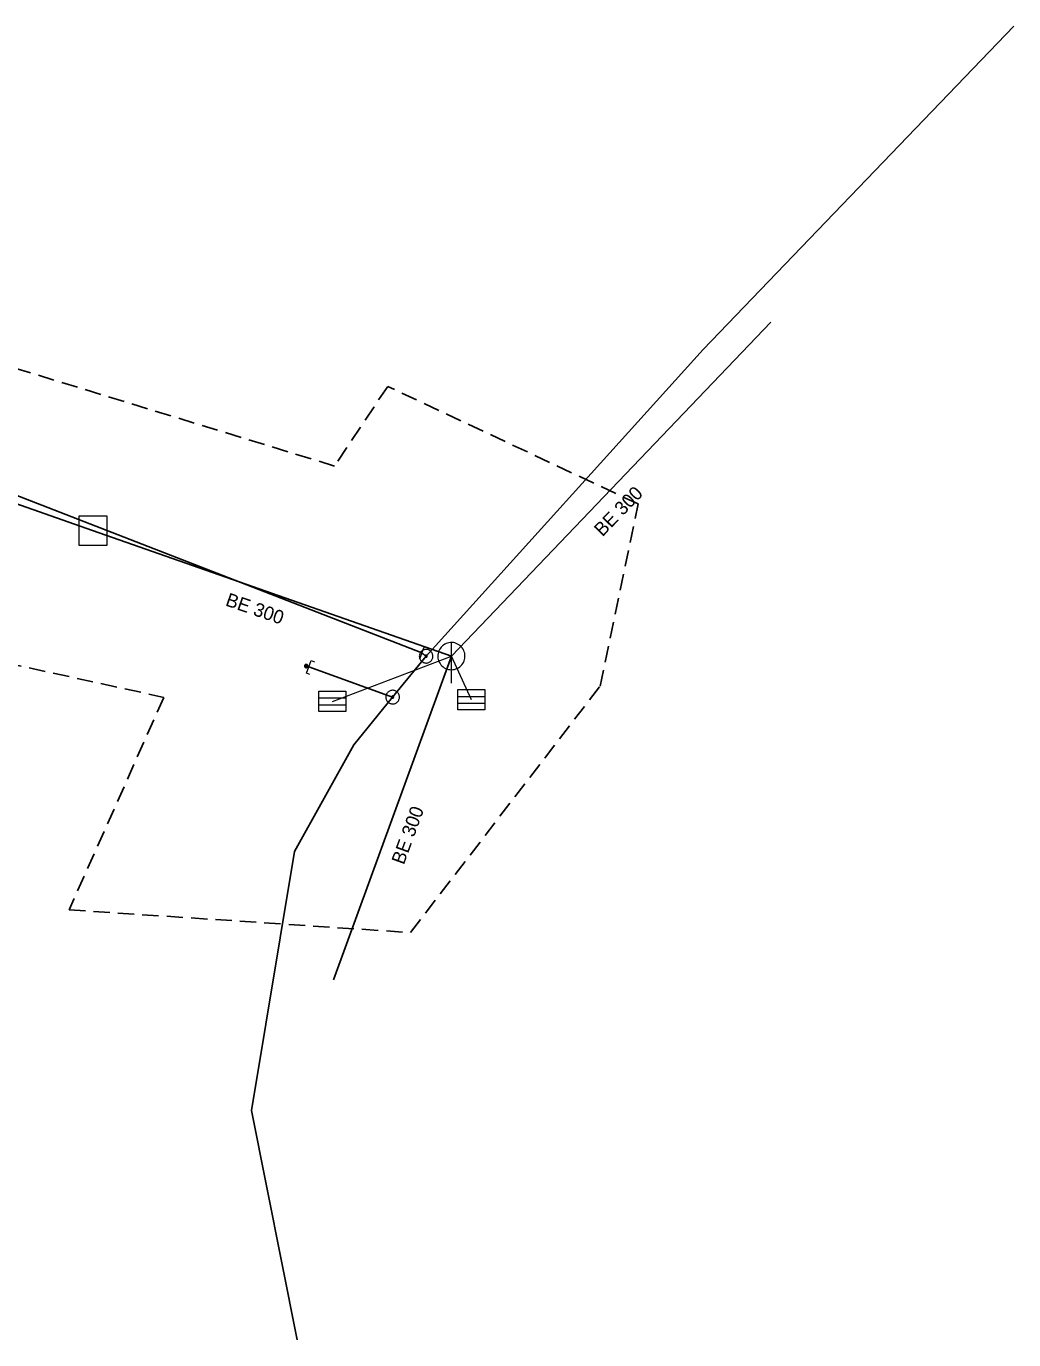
# Model space of a CAD drawing. Extents: x -687387 to -687009, y -972789 to -972578.
# Drawn here: x -687081.2 to -687008.6, y -972748.8 to -972652.2 of the extents above; entities that cross this region are included whole.
import ezdxf

# ---------------------------------------------------------------- set-up
doc = ezdxf.new("R2010")
doc.units = 0
doc.header["$LTSCALE"] = 0.4
doc.linetypes.add('MEDIUM_DASHED', pattern=[4.5, 3, -1.5])
doc.layers.add('1', color=7, linetype='Continuous')
for name, color, linetype, lineweight in [('11', 7, 'Continuous', 13), ('14', 7, 'Continuous', 25), ('17', 7, 'Continuous', 25), ('22', 7, 'Continuous', 13), ('34', 7, 'Continuous', 13), ('47', 7, 'Continuous', 13), ('63', 7, 'MEDIUM_DASHED', 25), ('9', 7, 'Continuous', 13)]:
    doc.layers.add(name, color=color, linetype=linetype, lineweight=lineweight)

msp = doc.modelspace()

# ---------------------------------------------------------------- linework, layer by layer
at = {"layer": '11'}
for p in [(-687058.699, -972701.867), (-687048.473, -972701.748)]:
    msp.add_line(p, (-687049.947, -972698.528), dxfattribs=at)
at = {"layer": '14'}
for p, q in [((-687026.435, -972673.962), (-687049.947, -972698.529)), ((-687076.354, -972689.285), (-687084.556, -972686.414)), ((-687049.947, -972698.528), (-687076.354, -972689.285)), ((-687058.628, -972722.345), (-687049.947, -972698.529))]:
    msp.add_line(p, q, dxfattribs=at)
at = {"layer": '14', "lineweight": 13}
for p, q in [((-687052.118, -972698.285), (-687051.808, -972698.538)), ((-687060.435, -972699.324), (-687060.629, -972699.259))]:
    msp.add_line(p, q, dxfattribs=at)
at = {"layer": '17'}
msp.add_line((-687054.27, -972701.546), (-687051.808, -972698.538), dxfattribs=at)
for points in [[(-687051.808, -972698.538), (-687031.429, -972675.969), (-687008.568, -972652.178)], [(-687137.189, -972675.528), (-687101.625, -972681.079), (-687082.6, -972686.438), (-687052.118, -972698.285)], [(-687061.305, -972748.839), (-687064.669, -972731.96), (-687061.487, -972712.912), (-687057.138, -972705.05), (-687054.27, -972701.546), (-687060.435, -972699.324)]]:
    msp.add_lwpolyline(points, dxfattribs=at)
at = {"layer": '22'}
for p, q in [((-687049.947, -972700.529), (-687049.946, -972697.529)), ((-687049.484, -972701.491), (-687047.484, -972701.491)), ((-687059.71, -972701.61), (-687057.71, -972701.61)), ((-687059.71, -972702.11), (-687057.71, -972702.11)), ((-687049.484, -972701.991), (-687047.484, -972701.991))]:
    msp.add_line(p, q, dxfattribs=at)
for points in [[(-687077.334, -972688.195), (-687075.301, -972688.195), (-687075.301, -972690.388), (-687077.334, -972690.388)], [(-687048.947, -972698.529), (-687048.952, -972698.42), (-687048.97, -972698.312), (-687049, -972698.206), (-687049.04, -972698.105), (-687049.092, -972698.008), (-687049.154, -972697.918), (-687049.226, -972697.835), (-687049.306, -972697.761), (-687049.394, -972697.695), (-687049.488, -972697.64), (-687049.588, -972697.595), (-687049.693, -972697.562), (-687049.8, -972697.54), (-687049.909, -972697.53), (-687050.019, -972697.532), (-687050.127, -972697.546), (-687050.234, -972697.571), (-687050.337, -972697.608), (-687050.435, -972697.657), (-687050.527, -972697.715), (-687050.613, -972697.784), (-687050.69, -972697.861), (-687050.759, -972697.947), (-687050.818, -972698.039), (-687050.866, -972698.137), (-687050.903, -972698.24), (-687050.929, -972698.347), (-687050.943, -972698.455), (-687050.946, -972698.565), (-687050.936, -972698.674), (-687050.915, -972698.781), (-687050.881, -972698.885), (-687050.837, -972698.985), (-687050.782, -972699.08), (-687050.716, -972699.168), (-687050.642, -972699.248), (-687050.559, -972699.32), (-687050.469, -972699.382), (-687050.373, -972699.434), (-687050.271, -972699.475), (-687050.166, -972699.505), (-687050.058, -972699.523), (-687049.948, -972699.529), (-687049.839, -972699.523), (-687049.731, -972699.505), (-687049.626, -972699.476), (-687049.524, -972699.435), (-687049.427, -972699.383), (-687049.337, -972699.321), (-687049.254, -972699.25), (-687049.179, -972699.17), (-687049.114, -972699.082), (-687049.058, -972698.988), (-687049.014, -972698.888), (-687048.98, -972698.784), (-687048.958, -972698.676), (-687048.948, -972698.567)], [(-687059.71, -972701.11), (-687057.71, -972701.11), (-687057.71, -972702.61), (-687059.71, -972702.61)], [(-687049.484, -972700.991), (-687047.484, -972700.991), (-687047.484, -972702.491), (-687049.484, -972702.491)]]:
    msp.add_lwpolyline(points, close=True, dxfattribs=at)
at = {"layer": '34'}
msp.add_line((-687051.951, -972697.813), (-687052.285, -972698.755), dxfattribs=at)
at = {"layer": '47'}
for points in [[(-687051.46, -972698.178), (-687051.5, -972698.144), (-687051.543, -972698.114), (-687051.588, -972698.089), (-687051.636, -972698.068), (-687051.686, -972698.052), (-687051.738, -972698.043), (-687051.79, -972698.039), (-687051.842, -972698.04), (-687051.894, -972698.045), (-687051.945, -972698.057), (-687051.995, -972698.074), (-687052.042, -972698.097), (-687052.087, -972698.123), (-687052.129, -972698.155), (-687052.167, -972698.19), (-687052.201, -972698.23), (-687052.231, -972698.273), (-687052.257, -972698.319), (-687052.277, -972698.366), (-687052.293, -972698.416), (-687052.302, -972698.468), (-687052.307, -972698.521), (-687052.306, -972698.573), (-687052.3, -972698.624), (-687052.288, -972698.675), (-687052.271, -972698.725), (-687052.249, -972698.773), (-687052.222, -972698.817), (-687052.19, -972698.859), (-687052.155, -972698.897), (-687052.115, -972698.931), (-687052.072, -972698.961), (-687052.027, -972698.988), (-687051.979, -972699.007), (-687051.929, -972699.023), (-687051.877, -972699.033), (-687051.825, -972699.038), (-687051.773, -972699.037), (-687051.721, -972699.03), (-687051.67, -972699.018), (-687051.62, -972699.001), (-687051.573, -972698.98), (-687051.528, -972698.952), (-687051.486, -972698.92), (-687051.448, -972698.885), (-687051.414, -972698.845), (-687051.384, -972698.802), (-687051.358, -972698.758), (-687051.338, -972698.709), (-687051.322, -972698.659), (-687051.312, -972698.607), (-687051.308, -972698.556), (-687051.309, -972698.503), (-687051.315, -972698.451), (-687051.327, -972698.4), (-687051.344, -972698.35), (-687051.366, -972698.304), (-687051.393, -972698.258), (-687051.425, -972698.216)], [(-687051.751, -972698.479), (-687051.757, -972698.472), (-687051.764, -972698.468), (-687051.771, -972698.464), (-687051.779, -972698.461), (-687051.788, -972698.458), (-687051.796, -972698.457), (-687051.805, -972698.455), (-687051.813, -972698.456), (-687051.822, -972698.457), (-687051.83, -972698.459), (-687051.839, -972698.462), (-687051.846, -972698.465), (-687051.853, -972698.47), (-687051.86, -972698.474), (-687051.866, -972698.481), (-687051.873, -972698.487), (-687051.877, -972698.494), (-687051.881, -972698.501), (-687051.884, -972698.509), (-687051.887, -972698.518), (-687051.888, -972698.526), (-687051.89, -972698.535), (-687051.889, -972698.543), (-687051.889, -972698.552), (-687051.886, -972698.56), (-687051.883, -972698.569), (-687051.88, -972698.576), (-687051.875, -972698.583), (-687051.871, -972698.59), (-687051.864, -972698.596), (-687051.858, -972698.603), (-687051.851, -972698.607), (-687051.844, -972698.611), (-687051.836, -972698.614), (-687051.827, -972698.617), (-687051.82, -972698.619), (-687051.81, -972698.62), (-687051.802, -972698.619), (-687051.793, -972698.619), (-687051.785, -972698.616), (-687051.776, -972698.613), (-687051.769, -972698.61), (-687051.762, -972698.605), (-687051.755, -972698.601), (-687051.749, -972698.594), (-687051.742, -972698.588), (-687051.738, -972698.581), (-687051.734, -972698.574), (-687051.731, -972698.566), (-687051.728, -972698.557), (-687051.726, -972698.55), (-687051.725, -972698.54), (-687051.726, -972698.532), (-687051.727, -972698.523), (-687051.729, -972698.515), (-687051.732, -972698.506), (-687051.735, -972698.499), (-687051.74, -972698.492), (-687051.744, -972698.485)], [(-687053.953, -972701.159), (-687053.995, -972701.128), (-687054.04, -972701.101), (-687054.088, -972701.08), (-687054.137, -972701.063), (-687054.189, -972701.052), (-687054.241, -972701.047), (-687054.293, -972701.047), (-687054.345, -972701.052), (-687054.396, -972701.062), (-687054.446, -972701.078), (-687054.495, -972701.099), (-687054.54, -972701.125), (-687054.582, -972701.155), (-687054.621, -972701.19), (-687054.656, -972701.229), (-687054.687, -972701.271), (-687054.714, -972701.316), (-687054.735, -972701.365), (-687054.752, -972701.413), (-687054.763, -972701.465), (-687054.768, -972701.517), (-687054.769, -972701.57), (-687054.764, -972701.622), (-687054.754, -972701.673), (-687054.737, -972701.722), (-687054.716, -972701.771), (-687054.69, -972701.816), (-687054.66, -972701.858), (-687054.625, -972701.897), (-687054.586, -972701.932), (-687054.544, -972701.963), (-687054.499, -972701.99), (-687054.451, -972702.012), (-687054.402, -972702.028), (-687054.35, -972702.039), (-687054.298, -972702.045), (-687054.246, -972702.046), (-687054.194, -972702.04), (-687054.142, -972702.03), (-687054.093, -972702.013), (-687054.044, -972701.992), (-687053.999, -972701.967), (-687053.957, -972701.936), (-687053.918, -972701.901), (-687053.883, -972701.862), (-687053.852, -972701.82), (-687053.825, -972701.775), (-687053.804, -972701.728), (-687053.787, -972701.678), (-687053.776, -972701.626), (-687053.77, -972701.574), (-687053.77, -972701.523), (-687053.775, -972701.471), (-687053.786, -972701.419), (-687053.802, -972701.369), (-687053.823, -972701.32), (-687053.849, -972701.276), (-687053.879, -972701.233), (-687053.914, -972701.194)], [(-687054.218, -972701.482), (-687054.225, -972701.476), (-687054.232, -972701.473), (-687054.239, -972701.469), (-687054.248, -972701.467), (-687054.256, -972701.465), (-687054.265, -972701.464), (-687054.273, -972701.463), (-687054.282, -972701.464), (-687054.29, -972701.467), (-687054.298, -972701.469), (-687054.307, -972701.472), (-687054.314, -972701.477), (-687054.321, -972701.482), (-687054.327, -972701.487), (-687054.333, -972701.494), (-687054.339, -972701.501), (-687054.342, -972701.508), (-687054.346, -972701.515), (-687054.348, -972701.524), (-687054.35, -972701.532), (-687054.351, -972701.541), (-687054.352, -972701.549), (-687054.351, -972701.558), (-687054.349, -972701.567), (-687054.346, -972701.574), (-687054.343, -972701.583), (-687054.338, -972701.59), (-687054.333, -972701.597), (-687054.328, -972701.603), (-687054.321, -972701.609), (-687054.314, -972701.615), (-687054.307, -972701.618), (-687054.3, -972701.622), (-687054.291, -972701.624), (-687054.283, -972701.626), (-687054.275, -972701.628), (-687054.266, -972701.628), (-687054.257, -972701.627), (-687054.248, -972701.625), (-687054.241, -972701.622), (-687054.232, -972701.619), (-687054.225, -972701.614), (-687054.218, -972701.609), (-687054.212, -972701.604), (-687054.206, -972701.597), (-687054.2, -972701.59), (-687054.197, -972701.583), (-687054.193, -972701.576), (-687054.191, -972701.567), (-687054.189, -972701.559), (-687054.187, -972701.551), (-687054.187, -972701.542), (-687054.188, -972701.533), (-687054.191, -972701.525), (-687054.193, -972701.517), (-687054.196, -972701.508), (-687054.201, -972701.501), (-687054.206, -972701.494), (-687054.211, -972701.488)]]:
    msp.add_lwpolyline(points, close=True, dxfattribs=at)
msp.add_lwpolyline([(-687060.366, -972699.876), (-687060.603, -972699.79), (-687060.266, -972698.857), (-687060.029, -972698.942)], dxfattribs=at)
at = {"layer": '63'}
msp.add_lwpolyline([(-687198.94, -972690.124), (-687142.558, -972685.938), (-687142.558, -972685.938), (-687071.103, -972701.568), (-687071.103, -972701.568), (-687078.081, -972717.199), (-687078.081, -972717.199), (-687052.96, -972718.874), (-687052.96, -972718.874), (-687039.004, -972700.731), (-687039.004, -972700.731), (-687036.212, -972687.333), (-687036.212, -972687.333), (-687054.635, -972678.68), (-687054.635, -972678.68), (-687058.542, -972684.542), (-687058.542, -972684.542), (-687096.782, -972672.819), (-687096.782, -972672.819), (-687147.303, -972666.399), (-687147.303, -972666.399), (-687234.11, -972667.795)], dxfattribs=at)
at = {"layer": '9'}
for points in [[(-687060.755, -972699.259), (-687060.755, -972699.272), (-687060.752, -972699.285), (-687060.75, -972699.298), (-687060.745, -972699.31), (-687060.739, -972699.322), (-687060.732, -972699.333), (-687060.723, -972699.343), (-687060.713, -972699.353), (-687060.703, -972699.361), (-687060.693, -972699.368), (-687060.681, -972699.374), (-687060.669, -972699.379), (-687060.656, -972699.382), (-687060.642, -972699.384), (-687060.63, -972699.386), (-687060.617, -972699.385), (-687060.603, -972699.383), (-687060.591, -972699.38), (-687060.578, -972699.375), (-687060.566, -972699.369), (-687060.556, -972699.362), (-687060.546, -972699.354), (-687060.536, -972699.344), (-687060.527, -972699.334), (-687060.521, -972699.323), (-687060.515, -972699.311), (-687060.51, -972699.299), (-687060.507, -972699.286), (-687060.505, -972699.273), (-687060.502, -972699.26), (-687060.504, -972699.247), (-687060.505, -972699.234), (-687060.509, -972699.221), (-687060.514, -972699.209), (-687060.519, -972699.197), (-687060.527, -972699.186), (-687060.534, -972699.176), (-687060.544, -972699.166), (-687060.554, -972699.158), (-687060.566, -972699.151), (-687060.578, -972699.145), (-687060.59, -972699.14), (-687060.603, -972699.137), (-687060.615, -972699.135), (-687060.629, -972699.134), (-687060.642, -972699.134), (-687060.654, -972699.136), (-687060.668, -972699.139), (-687060.679, -972699.144), (-687060.691, -972699.15), (-687060.703, -972699.157), (-687060.713, -972699.165), (-687060.723, -972699.175), (-687060.73, -972699.185), (-687060.738, -972699.196), (-687060.744, -972699.208), (-687060.749, -972699.22), (-687060.752, -972699.233), (-687060.754, -972699.246)], [(-687060.735, -972699.259), (-687060.735, -972699.27), (-687060.733, -972699.281), (-687060.73, -972699.292), (-687060.727, -972699.302), (-687060.722, -972699.312), (-687060.716, -972699.321), (-687060.708, -972699.33), (-687060.701, -972699.338), (-687060.691, -972699.345), (-687060.683, -972699.351), (-687060.673, -972699.356), (-687060.663, -972699.36), (-687060.652, -972699.363), (-687060.641, -972699.366), (-687060.63, -972699.366), (-687060.619, -972699.366), (-687060.608, -972699.364), (-687060.597, -972699.361), (-687060.587, -972699.357), (-687060.576, -972699.352), (-687060.568, -972699.346), (-687060.559, -972699.339), (-687060.551, -972699.331), (-687060.544, -972699.322), (-687060.538, -972699.313), (-687060.532, -972699.303), (-687060.529, -972699.293), (-687060.526, -972699.282), (-687060.524, -972699.271), (-687060.522, -972699.26), (-687060.522, -972699.249), (-687060.524, -972699.238), (-687060.527, -972699.227), (-687060.532, -972699.217), (-687060.537, -972699.207), (-687060.543, -972699.198), (-687060.549, -972699.189), (-687060.558, -972699.181), (-687060.566, -972699.174), (-687060.576, -972699.168), (-687060.586, -972699.163), (-687060.595, -972699.159), (-687060.607, -972699.156), (-687060.617, -972699.154), (-687060.629, -972699.154), (-687060.64, -972699.153), (-687060.651, -972699.155), (-687060.662, -972699.158), (-687060.671, -972699.162), (-687060.681, -972699.167), (-687060.691, -972699.173), (-687060.7, -972699.18), (-687060.708, -972699.188), (-687060.715, -972699.197), (-687060.72, -972699.206), (-687060.725, -972699.216), (-687060.73, -972699.226), (-687060.733, -972699.237), (-687060.735, -972699.248)], [(-687060.716, -972699.259), (-687060.716, -972699.268), (-687060.715, -972699.277), (-687060.712, -972699.286), (-687060.708, -972699.294), (-687060.705, -972699.302), (-687060.7, -972699.31), (-687060.693, -972699.317), (-687060.688, -972699.323), (-687060.681, -972699.329), (-687060.673, -972699.334), (-687060.664, -972699.338), (-687060.657, -972699.341), (-687060.647, -972699.344), (-687060.639, -972699.345), (-687060.63, -972699.347), (-687060.62, -972699.346), (-687060.612, -972699.345), (-687060.603, -972699.342), (-687060.595, -972699.339), (-687060.587, -972699.335), (-687060.578, -972699.33), (-687060.571, -972699.324), (-687060.566, -972699.318), (-687060.559, -972699.311), (-687060.554, -972699.303), (-687060.551, -972699.295), (-687060.548, -972699.287), (-687060.544, -972699.278), (-687060.544, -972699.269), (-687060.541, -972699.26), (-687060.543, -972699.251), (-687060.544, -972699.242), (-687060.546, -972699.233), (-687060.549, -972699.225), (-687060.554, -972699.217), (-687060.559, -972699.209), (-687060.565, -972699.202), (-687060.571, -972699.196), (-687060.578, -972699.19), (-687060.586, -972699.185), (-687060.593, -972699.181), (-687060.602, -972699.178), (-687060.61, -972699.175), (-687060.62, -972699.174), (-687060.629, -972699.173), (-687060.637, -972699.173), (-687060.647, -972699.174), (-687060.656, -972699.177), (-687060.664, -972699.18), (-687060.671, -972699.184), (-687060.679, -972699.189), (-687060.686, -972699.195), (-687060.693, -972699.201), (-687060.698, -972699.208), (-687060.703, -972699.216), (-687060.708, -972699.224), (-687060.711, -972699.232), (-687060.713, -972699.241), (-687060.715, -972699.25)], [(-687060.696, -972699.259), (-687060.696, -972699.266), (-687060.695, -972699.273), (-687060.693, -972699.28), (-687060.691, -972699.286), (-687060.688, -972699.292), (-687060.684, -972699.298), (-687060.679, -972699.304), (-687060.674, -972699.309), (-687060.669, -972699.313), (-687060.663, -972699.317), (-687060.657, -972699.32), (-687060.651, -972699.323), (-687060.644, -972699.324), (-687060.637, -972699.327), (-687060.63, -972699.327), (-687060.622, -972699.327), (-687060.615, -972699.325), (-687060.608, -972699.324), (-687060.603, -972699.321), (-687060.595, -972699.318), (-687060.591, -972699.314), (-687060.585, -972699.31), (-687060.58, -972699.305), (-687060.576, -972699.299), (-687060.571, -972699.293), (-687060.568, -972699.287), (-687060.566, -972699.281), (-687060.564, -972699.274), (-687060.563, -972699.267), (-687060.561, -972699.26), (-687060.561, -972699.253), (-687060.563, -972699.246), (-687060.565, -972699.239), (-687060.568, -972699.233), (-687060.571, -972699.226), (-687060.575, -972699.221), (-687060.578, -972699.215), (-687060.583, -972699.21), (-687060.59, -972699.206), (-687060.595, -972699.202), (-687060.602, -972699.199), (-687060.608, -972699.196), (-687060.615, -972699.194), (-687060.622, -972699.193), (-687060.629, -972699.193), (-687060.636, -972699.193), (-687060.642, -972699.193), (-687060.649, -972699.195), (-687060.656, -972699.198), (-687060.662, -972699.201), (-687060.668, -972699.205), (-687060.674, -972699.209), (-687060.679, -972699.214), (-687060.683, -972699.22), (-687060.686, -972699.225), (-687060.69, -972699.232), (-687060.693, -972699.238), (-687060.693, -972699.245), (-687060.696, -972699.252)], [(-687060.676, -972699.259), (-687060.676, -972699.264), (-687060.676, -972699.269), (-687060.674, -972699.274), (-687060.673, -972699.278), (-687060.671, -972699.283), (-687060.668, -972699.287), (-687060.664, -972699.29), (-687060.661, -972699.294), (-687060.657, -972699.297), (-687060.654, -972699.3), (-687060.649, -972699.302), (-687060.644, -972699.304), (-687060.64, -972699.305), (-687060.635, -972699.307), (-687060.63, -972699.307), (-687060.625, -972699.307), (-687060.62, -972699.306), (-687060.615, -972699.305), (-687060.61, -972699.303), (-687060.605, -972699.301), (-687060.602, -972699.298), (-687060.598, -972699.295), (-687060.595, -972699.291), (-687060.592, -972699.288), (-687060.588, -972699.284), (-687060.587, -972699.279), (-687060.585, -972699.275), (-687060.583, -972699.27), (-687060.583, -972699.265), (-687060.581, -972699.26), (-687060.581, -972699.255), (-687060.583, -972699.25), (-687060.583, -972699.245), (-687060.586, -972699.241), (-687060.588, -972699.236), (-687060.591, -972699.232), (-687060.593, -972699.228), (-687060.597, -972699.225), (-687060.6, -972699.222), (-687060.605, -972699.219), (-687060.61, -972699.217), (-687060.614, -972699.215), (-687060.619, -972699.214), (-687060.624, -972699.213), (-687060.629, -972699.213), (-687060.634, -972699.213), (-687060.639, -972699.214), (-687060.644, -972699.214), (-687060.647, -972699.216), (-687060.652, -972699.218), (-687060.657, -972699.221), (-687060.659, -972699.224), (-687060.664, -972699.227), (-687060.666, -972699.231), (-687060.669, -972699.235), (-687060.671, -972699.24), (-687060.674, -972699.244), (-687060.674, -972699.249), (-687060.676, -972699.254)], [(-687060.656, -972699.259), (-687060.656, -972699.262), (-687060.657, -972699.265), (-687060.656, -972699.267), (-687060.654, -972699.27), (-687060.654, -972699.273), (-687060.652, -972699.275), (-687060.649, -972699.277), (-687060.647, -972699.279), (-687060.646, -972699.281), (-687060.644, -972699.283), (-687060.641, -972699.285), (-687060.637, -972699.286), (-687060.636, -972699.286), (-687060.632, -972699.287), (-687060.63, -972699.287), (-687060.627, -972699.287), (-687060.624, -972699.287), (-687060.62, -972699.286), (-687060.619, -972699.285), (-687060.615, -972699.284), (-687060.614, -972699.282), (-687060.61, -972699.28), (-687060.608, -972699.278), (-687060.608, -972699.276), (-687060.605, -972699.274), (-687060.605, -972699.271), (-687060.603, -972699.268), (-687060.603, -972699.266), (-687060.602, -972699.263), (-687060.6, -972699.26), (-687060.602, -972699.257), (-687060.602, -972699.254), (-687060.603, -972699.251), (-687060.603, -972699.249), (-687060.605, -972699.246), (-687060.607, -972699.244), (-687060.608, -972699.241), (-687060.61, -972699.239), (-687060.613, -972699.238), (-687060.615, -972699.236), (-687060.617, -972699.235), (-687060.62, -972699.234), (-687060.622, -972699.233), (-687060.625, -972699.233), (-687060.629, -972699.232), (-687060.632, -972699.233), (-687060.635, -972699.232), (-687060.637, -972699.234), (-687060.64, -972699.234), (-687060.642, -972699.235), (-687060.644, -972699.237), (-687060.647, -972699.238), (-687060.649, -972699.24), (-687060.651, -972699.243), (-687060.652, -972699.245), (-687060.654, -972699.248), (-687060.654, -972699.25), (-687060.656, -972699.253), (-687060.656, -972699.256)], [(-687060.637, -972699.259), (-687060.637, -972699.261), (-687060.637, -972699.261), (-687060.636, -972699.261), (-687060.636, -972699.263), (-687060.637, -972699.264), (-687060.635, -972699.264), (-687060.635, -972699.264), (-687060.635, -972699.266), (-687060.635, -972699.266), (-687060.634, -972699.267), (-687060.632, -972699.267), (-687060.632, -972699.267), (-687060.632, -972699.268), (-687060.63, -972699.268), (-687060.63, -972699.268), (-687060.629, -972699.268), (-687060.627, -972699.268), (-687060.627, -972699.267), (-687060.627, -972699.267), (-687060.625, -972699.267), (-687060.625, -972699.266), (-687060.625, -972699.266), (-687060.624, -972699.265), (-687060.624, -972699.265), (-687060.622, -972699.264), (-687060.622, -972699.263), (-687060.62, -972699.262), (-687060.62, -972699.262), (-687060.62, -972699.261), (-687060.62, -972699.26), (-687060.62, -972699.259), (-687060.62, -972699.258), (-687060.62, -972699.258), (-687060.622, -972699.257), (-687060.622, -972699.256), (-687060.622, -972699.255), (-687060.622, -972699.255), (-687060.624, -972699.254), (-687060.624, -972699.254), (-687060.625, -972699.253), (-687060.625, -972699.253), (-687060.627, -972699.252), (-687060.627, -972699.252), (-687060.627, -972699.252), (-687060.629, -972699.252), (-687060.63, -972699.252), (-687060.63, -972699.252), (-687060.63, -972699.252), (-687060.632, -972699.253), (-687060.632, -972699.252), (-687060.634, -972699.254), (-687060.634, -972699.254), (-687060.635, -972699.254), (-687060.635, -972699.254), (-687060.636, -972699.256), (-687060.636, -972699.257), (-687060.636, -972699.258), (-687060.637, -972699.258), (-687060.637, -972699.259)]]:
    msp.add_lwpolyline(points, close=True, dxfattribs=at)

# ---------------------------------------------------------------- texts
at = {"layer": '1'}
for rotation, p in [(46, (-687038.83, -972689.785)), (341, (-687066.637, -972694.789)), (70, (-687053.448, -972713.934))]:
    msp.add_text('BE 300', height=1, rotation=rotation, dxfattribs=at).set_placement(p)

doc.saveas('drawing.dxf')
